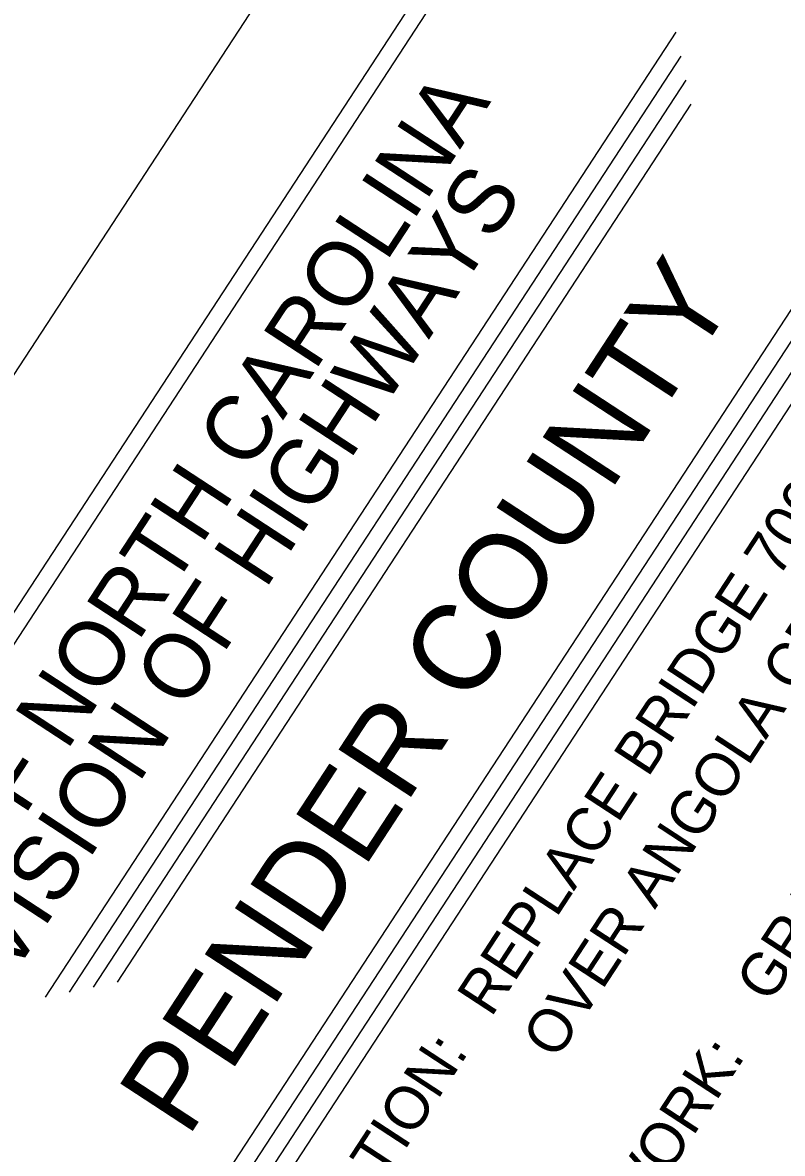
# Model space of a CAD drawing. Extents: x 1190029 to 2382315, y 163128 to 334830.
# Drawn here: x 2379548 to 2379987, y 332677 to 333329 of the extents above; entities that cross this region are included whole.
import ezdxf

# ---------------------------------------------------------------- set-up
doc = ezdxf.new("R2010")
doc.units = 0
for name, color, linetype in [('_CIVIL_CONSTRUCTION', 7, 'Continuous'), ('Exist Utilities Telephone UG FO SUE LOS B Text', 7, 'Continuous'), ('Sheet_Plan_CELL', 7, 'Continuous'), ('z - Construction', 7, 'Continuous')]:
    doc.layers.add(name, color=color, linetype=linetype)

msp = doc.modelspace()

# ---------------------------------------------------------------- linework, layer by layer
at = {"layer": '_CIVIL_CONSTRUCTION'}
msp.add_line((2379839.76, 332985.72), (2379839.76, 332985.72), dxfattribs=at)
at = {"layer": 'Exist Utilities Telephone UG FO SUE LOS B Text'}
for p, q in [((2380483.91, 334428.71), (2378727.4, 331741.94)), ((2380486.93, 334414.79), (2378796.08, 331828.46)), ((2379561.12, 332766.7), (2379925.26, 333323.74)), ((2379629.9, 332610.26), (2380096.14, 333323.37)), ((2379574.94, 332769.61), (2379928.18, 333309.88)), ((2379643.75, 332613.16), (2380099.04, 333309.53)), ((2379588.8, 332772.49), (2379931.06, 333296.05)), ((2379657.61, 332616.04), (2380101.91, 333295.7)), ((2379602.65, 332775.39), (2379933.95, 333282.21)), ((2379671.43, 332618.95), (2380104.83, 333281.85))]:
    msp.add_line(p, q, dxfattribs=at)
at = {"layer": 'z - Construction'}
msp.add_line((2380473.12, 334549.26), (2378612.64, 331703.46), dxfattribs=at)

# ---------------------------------------------------------------- texts
at = {"layer": 'Exist Utilities Telephone UG FO SUE LOS B Text'}
for s, height, p in [('STATE OF NORTH CAROLINA', 37.4998, (2379431.4, 332691.41)), ('DIVISION OF HIGHWAYS', 37.4998, (2379514.07, 332735.62)), ('LOCATION: ', 25, (2379707.11, 332584.16)), ('TYPE OF WORK:', 25.0002, (2379820.12, 332510.28))]:
    msp.add_text(s, height=height, rotation=56.82484, dxfattribs=at).set_placement(p)
at = {"layer": 'Sheet_Plan_CELL'}
for s, height, p in [('REPLACE BRIDGE 700037 ON NC 53          ', 25.0002, (2379818.37, 332754.53)), ('        PENDER COUNTY        ', 50, (2379561.78, 332560.51)), ('GRADING, DRAINAGE, PAVING,              ', 25.0002, (2379979.33, 332762.44)), ('OVER ANGOLA CREEK                       ', 25.0002, (2379856.04, 332729.9))]:
    msp.add_text(s, height=height, rotation=56.82484, dxfattribs=at).set_placement(p)

doc.saveas('drawing.dxf')
